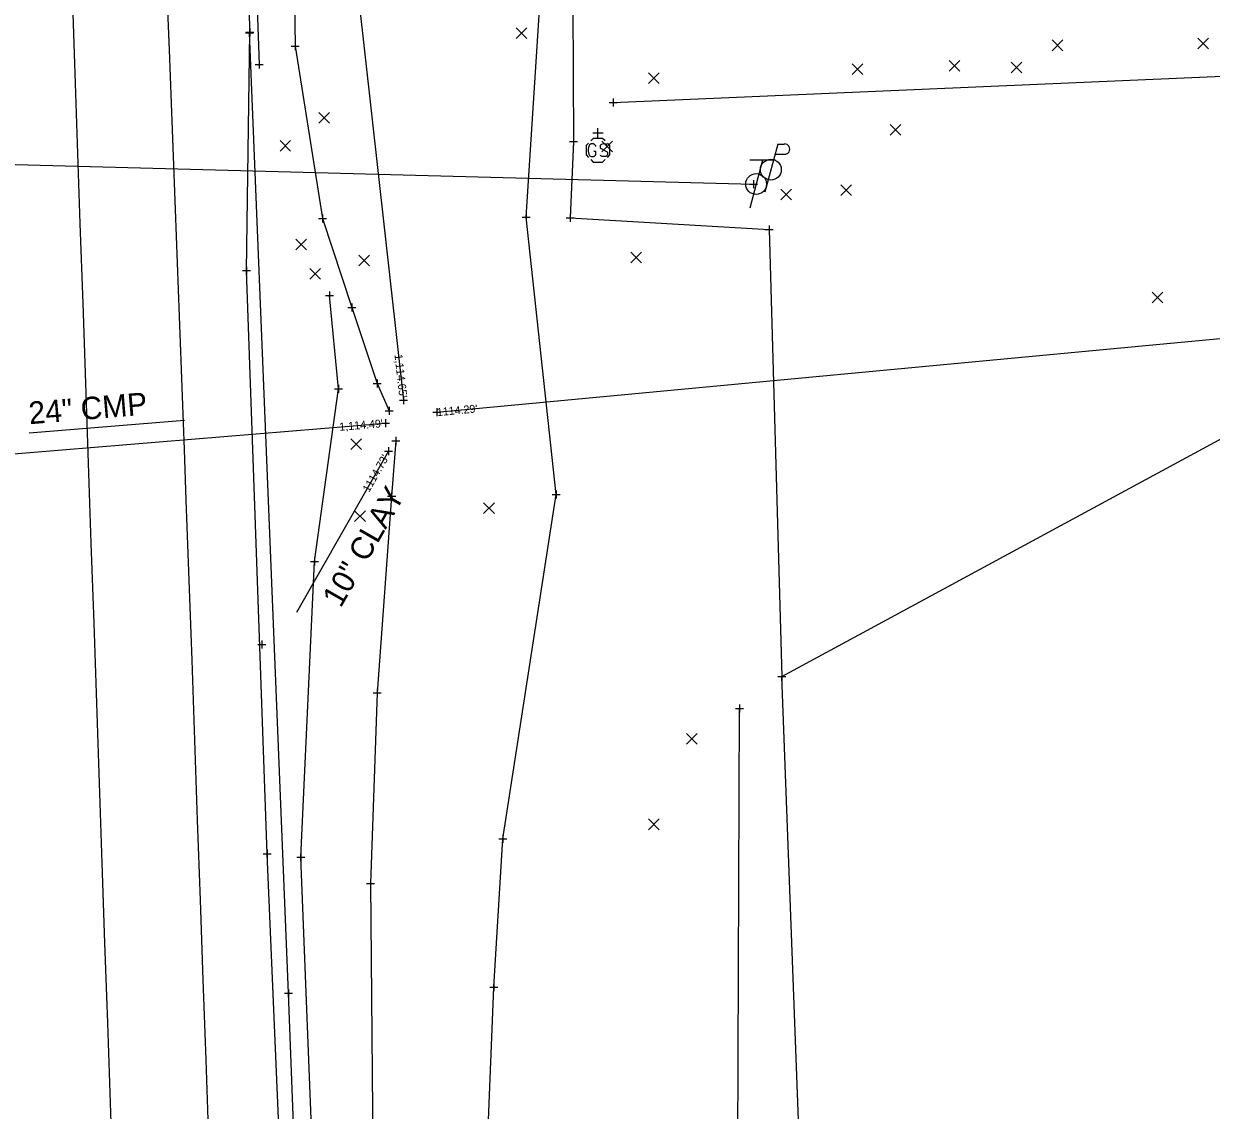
# Model space of a CAD drawing. Extents: x 146022 to 147632, y 437624 to 440659.
# Drawn here: x 147019.1 to 147167.5, y 438466 to 438601.8 of the extents above; entities that cross this region are included whole.
import ezdxf

# ---------------------------------------------------------------- set-up
doc = ezdxf.new("R2010")
doc.units = 0
for name, color, linetype in [('_CIVIL_CONSTRUCTION', 7, 'Continuous'), ('BR_P_Rail_Object', 7, 'Continuous'), ('DR_P_Paved_Gutter', 7, 'Continuous'), ('DR_P_Underdrain', 7, 'Continuous'), ('DR_X_Storm_Sewer', 7, 'Continuous'), ('DR_X_Text', 7, 'Continuous'), ('DT_X_Contour_Minor', 7, 'Continuous'), ('DT_X_Island', 7, 'Continuous'), ('GE_P_Alignment_100_Distances', 7, 'Continuous'), ('PF_X_Ground_Line', 7, 'Continuous'), ('PV_P_Curb', 7, 'Continuous'), ('RD_P_Anchor_Assembly', 7, 'Continuous'), ('RD_P_Fence', 7, 'Continuous'), ('RD_P_GR_Lt_Replaced', 7, 'Continuous'), ('SC_Scratch1', 7, 'Continuous'), ('SC_Scratch3', 7, 'Continuous'), ('SV_X_Terrain_Boundary', 7, 'Continuous'), ('UT_X_Overhead_Cable_TV', 7, 'Continuous'), ('UT_X_Overhead_Electric', 7, 'Continuous')]:
    doc.layers.add(name, color=color, linetype=linetype)

msp = doc.modelspace()

# ---------------------------------------------------------------- linework, layer by layer
at = {"layer": '_CIVIL_CONSTRUCTION'}
for p, q in [((147080.61, 438599.97), (147081.94, 438601.31)), ((147080.61, 438601.31), (147081.94, 438599.97)), ((147147.6, 438598.45), (147148.94, 438599.79)), ((147147.6, 438599.79), (147148.94, 438598.45)), ((147165.79, 438598.69), (147167.12, 438600.03)), ((147165.79, 438600.03), (147167.12, 438598.69)), ((147134.72, 438595.89), (147136.05, 438597.23)), ((147134.72, 438597.23), (147136.05, 438595.89)), ((147122.59, 438595.46), (147123.92, 438596.79)), ((147122.59, 438596.79), (147123.92, 438595.46)), ((147142.47, 438595.68), (147143.8, 438597.02)), ((147142.47, 438597.02), (147143.8, 438595.68)), ((147097.15, 438594.35), (147098.48, 438595.68)), ((147097.15, 438595.68), (147098.48, 438594.35)), ((147055.97, 438589.39), (147057.3, 438590.73)), ((147055.97, 438590.73), (147057.3, 438589.39)), ((147127.34, 438587.9), (147128.68, 438589.24)), ((147127.34, 438589.24), (147128.68, 438587.9)), ((147051.11, 438585.91), (147052.44, 438587.24)), ((147051.11, 438587.24), (147052.44, 438585.91)), ((147091.33, 438585.82), (147092.66, 438587.15)), ((147091.33, 438587.15), (147092.66, 438585.82)), ((147113.67, 438579.81), (147115, 438581.14)), ((147113.67, 438581.14), (147115, 438579.81)), ((147121.19, 438580.34), (147122.52, 438581.68)), ((147121.19, 438581.68), (147122.52, 438580.34)), ((147053.08, 438573.54), (147054.41, 438574.87)), ((147053.08, 438574.87), (147054.41, 438573.54)), ((147060.97, 438571.56), (147062.31, 438572.89)), ((147060.97, 438572.89), (147062.31, 438571.56)), ((147094.95, 438571.92), (147096.28, 438573.25)), ((147094.95, 438573.25), (147096.28, 438571.92)), ((147054.82, 438569.9), (147056.15, 438571.23)), ((147054.82, 438571.23), (147056.15, 438569.9)), ((147160.09, 438566.92), (147161.42, 438568.26)), ((147160.09, 438568.26), (147161.42, 438566.92)), ((147059.95, 438548.58), (147061.28, 438549.91)), ((147059.95, 438549.91), (147061.28, 438548.58)), ((147060.43, 438539.59), (147061.77, 438540.92)), ((147060.43, 438540.92), (147061.77, 438539.59)), ((147076.55, 438540.59), (147077.89, 438541.93)), ((147076.55, 438541.93), (147077.89, 438540.59)), ((147101.89, 438511.77), (147103.22, 438513.1)), ((147101.89, 438513.1), (147103.22, 438511.77)), ((147097.17, 438501.07), (147098.5, 438502.41)), ((147097.17, 438502.41), (147098.5, 438501.07))]:
    msp.add_line(p, q, dxfattribs=at)
at = {"layer": 'BR_P_Rail_Object'}
for points in [[(147087.56, 438608.65), (147087.7, 438604.08), (147087.8, 438587.11)], [(147087.8, 438587.11), (147087.36, 438577.55), (147112.21, 438576.1), (147113.81, 438520.22)], [(147119.79, 438362.73), (147118.32, 438400.57), (147116.48, 438449.21), (147113.81, 438520.22)]]:
    msp.add_lwpolyline(points, dxfattribs=at)
at = {"layer": 'DR_P_Paved_Gutter'}
msp.add_lwpolyline([(147056.84, 438400.98), (147054.81, 438411.86), (147052.17, 438480.63), (147047.3, 438600.68)], dxfattribs=at)
at = {"layer": 'DR_P_Underdrain'}
msp.add_lwpolyline([(147046.25, 438660.1), (147048.5, 438596.72)], dxfattribs=at)
at = {"layer": 'DR_X_Storm_Sewer'}
for p, q in [((147053.41, 438671.93), (147066.55, 438554.77)), ((147070.7, 438553.26), (147483.94, 438592.14)), ((146991.1, 438545.87), (147064.28, 438551.9)), ((147064.67, 438548.38), (147053.15, 438528.21))]:
    msp.add_line(p, q, dxfattribs=at)
msp.add_lwpolyline([(147092.74, 438591.99), (147202.64, 438596.73), (147314.7, 438595.59)], dxfattribs=at)
at = {"layer": 'DR_X_Text'}
msp.add_line((147039.19, 438552.24), (147019.78, 438550.64), dxfattribs=at)
at = {"layer": 'DT_X_Contour_Minor'}
for p, q in [((147113.3, 438586.78), (147111.69, 438580.78)), ((147113.3, 438586.78), (147114.15, 438586.78)), ((147112.96, 438585.51), (147114.15, 438585.51))]:
    msp.add_line(p, q, dxfattribs=at)
msp.add_circle((147112.44, 438583.58), 1.3, dxfattribs=at)
msp.add_arc((147114.16, 438586.15), 0.638, 268.8767, 91.1233, dxfattribs=at)
at = {"layer": 'DT_X_Island'}
for p, q in [((147090.83, 438587.49), (147090.83, 438588.76)), ((147091.47, 438588.13), (147090.19, 438588.13)), ((147090.83, 438586.01), (147090.83, 438586.01))]:
    msp.add_line(p, q, dxfattribs=at)
for points in [[(147089.65, 438586.91), (147089.35, 438586.6), (147089.35, 438585.42), (147089.65, 438585.12)], [(147090.57, 438586.49), (147090.56, 438586.56), (147090.52, 438586.62), (147090.46, 438586.68), (147090.37, 438586.76), (147090.31, 438586.78), (147090.26, 438586.8), (147090.18, 438586.81), (147090.03, 438586.81), (147089.97, 438586.8), (147089.93, 438586.78), (147089.88, 438586.76), (147089.78, 438586.68), (147089.72, 438586.59), (147089.68, 438586.49), (147089.65, 438586.36), (147089.63, 438586.15), (147089.63, 438585.89), (147089.64, 438585.68), (147089.69, 438585.51), (147089.77, 438585.36), (147089.83, 438585.31), (147089.9, 438585.26), (147090.04, 438585.21), (147090.18, 438585.21), (147090.32, 438585.23), (147090.37, 438585.26), (147090.42, 438585.28), (147090.47, 438585.34), (147090.52, 438585.41), (147090.57, 438585.52), (147090.57, 438585.84), (147090.31, 438585.84)], [(147091.73, 438587.19), (147091.42, 438587.49), (147090.24, 438587.49), (147089.93, 438587.19)], [(147091.97, 438586.7), (147091.95, 438586.72), (147091.91, 438586.75), (147091.79, 438586.78), (147091.66, 438586.81), (147091.56, 438586.81), (147091.52, 438586.81), (147091.35, 438586.77), (147091.21, 438586.7), (147091.13, 438586.59), (147091.1, 438586.49), (147091.1, 438586.42), (147091.13, 438586.32), (147091.23, 438586.23), (147091.92, 438585.85), (147091.98, 438585.8), (147092.01, 438585.75), (147092.03, 438585.68), (147092.03, 438585.6), (147092.02, 438585.52), (147092.01, 438585.47), (147091.98, 438585.41), (147091.96, 438585.36), (147091.93, 438585.32), (147091.9, 438585.28), (147091.86, 438585.26), (147091.81, 438585.23), (147091.77, 438585.22), (147091.66, 438585.21), (147091.48, 438585.21), (147091.37, 438585.23), (147091.2, 438585.32), (147091.1, 438585.4)], [(147092.01, 438585.12), (147092.31, 438585.42), (147092.31, 438586.6), (147092.01, 438586.91)], [(147089.93, 438584.84), (147090.24, 438584.53), (147091.42, 438584.53), (147091.73, 438584.83)]]:
    msp.add_lwpolyline(points, dxfattribs=at)
at = {"layer": 'GE_P_Alignment_100_Distances'}
msp.add_lwpolyline([(146878.79, 438588.15), (147008.47, 438584.5), (147008.59, 438584.46), (147110.26, 438581.75)], dxfattribs=at)
at = {"layer": 'PF_X_Ground_Line'}
msp.add_line((147074.02, 438388.21), (147077.83, 438481.37), dxfattribs=at)
for points in [[(147077.83, 438481.37), (147078.95, 438499.91), (147085.6, 438542.96), (147081.87, 438577.63), (147083.77, 438607.47)], [(147053.73, 438497.65), (147055.41, 438534.59), (147058.42, 438556.17), (147057.3, 438567.84)], [(147108.63, 438400.88), (147108.31, 438461.63), (147108.54, 438516.2)], [(147064.97, 438144.61), (147062.9, 438206.3), (147060.74, 438264.49), (147059.17, 438322.98), (147056.14, 438384.08), (147055.96, 438440.58), (147053.73, 438497.65)]]:
    msp.add_lwpolyline(points, dxfattribs=at)
at = {"layer": 'PV_P_Curb'}
msp.add_lwpolyline([(147030.27, 438456.93), (147029.93, 438466.92), (147029.58, 438476.91), (147029.24, 438486.91), (147028.9, 438496.9), (147028.55, 438506.9), (147028.21, 438516.89), (147027.87, 438526.88), (147027.53, 438536.88), (147027.18, 438546.87), (147026.84, 438556.87), (147026.5, 438566.86), (147026.15, 438576.85), (147025.81, 438586.85), (147025.47, 438596.84), (147025.12, 438606.84), (147025.04, 438609.21)], dxfattribs=at)
at = {"layer": 'RD_P_Anchor_Assembly'}
for p, q in [((147046.8, 438600.68), (147047.8, 438600.68)), ((147046.82, 438600.78), (147047.82, 438600.78)), ((147047.3, 438601.18), (147047.3, 438600.18)), ((147047.3, 438600.68), (147047.3, 438600.68)), ((147047.32, 438601.28), (147047.32, 438600.28)), ((147047.32, 438600.78), (147047.32, 438600.78)), ((147052.52, 438599), (147053.52, 438599)), ((147053.02, 438599.5), (147053.02, 438598.5)), ((147053.02, 438599), (147053.02, 438599)), ((147048.5, 438597.22), (147048.5, 438596.22)), ((147048, 438596.72), (147049, 438596.72)), ((147048.5, 438596.72), (147048.5, 438596.72)), ((147092.24, 438591.99), (147093.24, 438591.99)), ((147092.74, 438592.49), (147092.74, 438591.49)), ((147092.74, 438591.99), (147092.74, 438591.99)), ((147087.3, 438587.11), (147088.3, 438587.11)), ((147087.8, 438587.61), (147087.8, 438586.61)), ((147087.8, 438587.11), (147087.8, 438587.11)), ((147109.76, 438581.75), (147110.76, 438581.75)), ((147110.26, 438582.25), (147110.26, 438581.25)), ((147110.26, 438581.75), (147110.26, 438581.75)), ((147056.41, 438577.97), (147056.41, 438576.97)), ((147081.87, 438578.13), (147081.87, 438577.13)), ((147087.36, 438578.05), (147087.36, 438577.05)), ((147055.91, 438577.47), (147056.91, 438577.47)), ((147056.41, 438577.47), (147056.41, 438577.47)), ((147081.37, 438577.63), (147082.37, 438577.63)), ((147081.87, 438577.63), (147081.87, 438577.63)), ((147086.86, 438577.55), (147087.86, 438577.55)), ((147087.36, 438577.55), (147087.36, 438577.55)), ((147112.21, 438576.6), (147112.21, 438575.6)), ((147111.71, 438576.1), (147112.71, 438576.1)), ((147112.21, 438576.1), (147112.21, 438576.1)), ((147046.44, 438570.99), (147047.44, 438570.99)), ((147046.94, 438571.49), (147046.94, 438570.49)), ((147046.94, 438570.99), (147046.94, 438570.99)), ((147056.8, 438567.84), (147057.8, 438567.84)), ((147057.3, 438568.34), (147057.3, 438567.34)), ((147057.3, 438567.84), (147057.3, 438567.84)), ((147059.6, 438566.36), (147060.6, 438566.36)), ((147060.1, 438566.86), (147060.1, 438565.86)), ((147060.1, 438566.36), (147060.1, 438566.36)), ((147063.26, 438557.36), (147063.26, 438556.36)), ((147057.92, 438556.17), (147058.92, 438556.17)), ((147058.42, 438556.67), (147058.42, 438555.67)), ((147058.42, 438556.17), (147058.42, 438556.17)), ((147062.76, 438556.86), (147063.76, 438556.86)), ((147063.26, 438556.86), (147063.26, 438556.86)), ((147064.24, 438553.44), (147065.24, 438553.44)), ((147064.74, 438553.94), (147064.74, 438552.94)), ((147064.74, 438553.44), (147064.74, 438553.44)), ((147065.6, 438550.18), (147065.6, 438549.18)), ((147065.1, 438549.68), (147066.1, 438549.68)), ((147065.6, 438549.68), (147065.6, 438549.68)), ((147064.56, 438542.78), (147065.56, 438542.78)), ((147065.06, 438543.28), (147065.06, 438542.28)), ((147065.06, 438542.78), (147065.06, 438542.78)), ((147085.1, 438542.96), (147086.1, 438542.96)), ((147085.6, 438543.46), (147085.6, 438542.46)), ((147085.6, 438542.96), (147085.6, 438542.96)), ((147055.41, 438535.09), (147055.41, 438534.09)), ((147054.91, 438534.59), (147055.91, 438534.59)), ((147055.41, 438534.59), (147055.41, 438534.59)), ((147048.85, 438524.73), (147048.85, 438523.73)), ((147048.35, 438524.23), (147049.35, 438524.23)), ((147048.85, 438524.23), (147048.85, 438524.23)), ((147113.31, 438520.22), (147114.31, 438520.22)), ((147113.81, 438520.72), (147113.81, 438519.72)), ((147113.81, 438520.22), (147113.81, 438520.22)), ((147063.25, 438518.66), (147063.25, 438517.66)), ((147062.75, 438518.16), (147063.75, 438518.16)), ((147063.25, 438518.16), (147063.25, 438518.16)), ((147108.04, 438516.2), (147109.04, 438516.2)), ((147108.54, 438516.7), (147108.54, 438515.7)), ((147108.54, 438516.2), (147108.54, 438516.2)), ((147078.45, 438499.91), (147079.45, 438499.91)), ((147078.95, 438500.41), (147078.95, 438499.41)), ((147078.95, 438499.91), (147078.95, 438499.91)), ((147049.02, 438498.04), (147050.02, 438498.04)), ((147049.52, 438498.54), (147049.52, 438497.54)), ((147049.52, 438498.04), (147049.52, 438498.04)), ((147053.73, 438498.15), (147053.73, 438497.15)), ((147053.23, 438497.65), (147054.23, 438497.65)), ((147053.73, 438497.65), (147053.73, 438497.65)), ((147062.43, 438494.85), (147062.43, 438493.85)), ((147061.93, 438494.35), (147062.93, 438494.35)), ((147062.43, 438494.35), (147062.43, 438494.35)), ((147077.83, 438481.87), (147077.83, 438480.87)), ((147051.67, 438480.63), (147052.67, 438480.63)), ((147052.17, 438481.13), (147052.17, 438480.13)), ((147052.17, 438480.63), (147052.17, 438480.63)), ((147077.33, 438481.37), (147078.33, 438481.37)), ((147077.83, 438481.37), (147077.83, 438481.37))]:
    msp.add_line(p, q, dxfattribs=at)
at = {"layer": 'RD_P_Fence'}
for points in [[(147052.85, 438610.27), (147053.02, 438599), (147056.41, 438577.47), (147060.1, 438566.36), (147063.26, 438556.86), (147064.74, 438553.44)], [(147065.6, 438549.68), (147065.06, 438542.78), (147063.25, 438518.16), (147062.43, 438494.35), (147062.99, 438428.1), (147063.01, 438395.72)]]:
    msp.add_lwpolyline(points, dxfattribs=at)
at = {"layer": 'RD_P_GR_Lt_Replaced'}
for points in [[(147028.78, 439100.29), (147030.7, 439050.1), (147032.83, 438989.57), (147034.21, 438926.71), (147035.77, 438865.15), (147038.94, 438801.43), (147040.73, 438744.01), (147041.91, 438709.75), (147043.37, 438678.61), (147045.13, 438660.08), (147045.68, 438643.98), (147046.17, 438628.21), (147046.87, 438610.99), (147047.32, 438600.78)], [(147049.52, 438498.04), (147046.94, 438570.99), (147047.32, 438600.78)], [(147062.34, 438143.95), (147060.09, 438206), (147058.01, 438263.66), (147055.74, 438322.54), (147053.39, 438383.76), (147051.9, 438441.59), (147049.52, 438498.04)]]:
    msp.add_lwpolyline(points, dxfattribs=at)
at = {"layer": 'SC_Scratch3'}
msp.add_lwpolyline([(147036.86, 438608.56), (147037.24, 438598.57), (147037.62, 438588.57), (147037.99, 438578.58), (147038.37, 438568.59), (147038.75, 438558.6), (147039.13, 438548.6), (147039.36, 438542.25), (147039.72, 438532.26), (147040.07, 438522.26), (147040.42, 438512.27), (147040.77, 438502.27), (147041.12, 438492.28), (147041.47, 438482.29), (147041.82, 438472.29), (147042.18, 438462.3)], dxfattribs=at)
at = {"layer": 'SV_X_Terrain_Boundary'}
msp.add_lwpolyline([(147116.48, 438449.21), (147113.81, 438520.22), (147177.01, 438554.45)], dxfattribs=at)
at = {"layer": 'UT_X_Overhead_Cable_TV'}
for p, q in [((147113, 438584.78), (147109.8, 438584.78)), ((147111.4, 438584.78), (147109.8, 438578.78))]:
    msp.add_line(p, q, dxfattribs=at)
msp.add_circle((147110.6, 438581.78), 1.3, dxfattribs=at)
at = {"layer": 'UT_X_Overhead_Electric'}
for p, q in [((147066.05, 438554.77), (147067.05, 438554.77)), ((147066.55, 438555.27), (147066.55, 438554.27)), ((147066.55, 438554.77), (147066.55, 438554.77)), ((147070.2, 438553.26), (147071.2, 438553.26)), ((147070.7, 438553.76), (147070.7, 438552.76)), ((147070.7, 438553.26), (147070.7, 438553.26)), ((147063.78, 438551.9), (147064.78, 438551.9)), ((147064.28, 438552.4), (147064.28, 438551.4)), ((147064.28, 438551.9), (147064.28, 438551.9)), ((147064.17, 438548.38), (147065.17, 438548.38)), ((147064.67, 438548.88), (147064.67, 438547.88)), ((147064.67, 438548.38), (147064.67, 438548.38))]:
    msp.add_line(p, q, dxfattribs=at)

# ---------------------------------------------------------------- texts
at = {"layer": 'DR_X_Text'}
for s, rotation, p in [('24" CMP', 4.708, (147019.81, 438551.75)), ('10" CLAY', 60.2496, (147058.69, 438528.7))]:
    msp.add_text(s, height=2.8, rotation=rotation, dxfattribs=at).set_placement(p)
at = {"layer": 'SC_Scratch1'}
for s, rotation, p in [("1,114.65'", 276.3984, (147065.41, 438560.46)), ("1114.29'", 5.3754, (147070.75, 438552.76)), ("1,114.49'", 4.708, (147058.56, 438550.93)), ("1114.73'", 60.2496, (147062.23, 438543.17))]:
    msp.add_text(s, height=1, rotation=rotation, dxfattribs=at).set_placement(p)

doc.saveas('drawing.dxf')
